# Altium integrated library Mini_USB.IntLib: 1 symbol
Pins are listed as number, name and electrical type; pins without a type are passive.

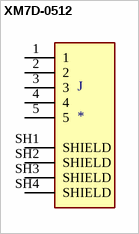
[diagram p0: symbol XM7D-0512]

## XM7D-0512
designator J
USB - mini B USB 2.0 Receptacle Connector 5 Position Through Hole, Right Angle; MF: Omron Electronics; MP: XM7D-0512
footprint OMRON_XM7D-0512
pins: 1, 2, 3, 4, 5, SH1 SHIELD, SH2 SHIELD, SH3 SHIELD, SH4 SHIELD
